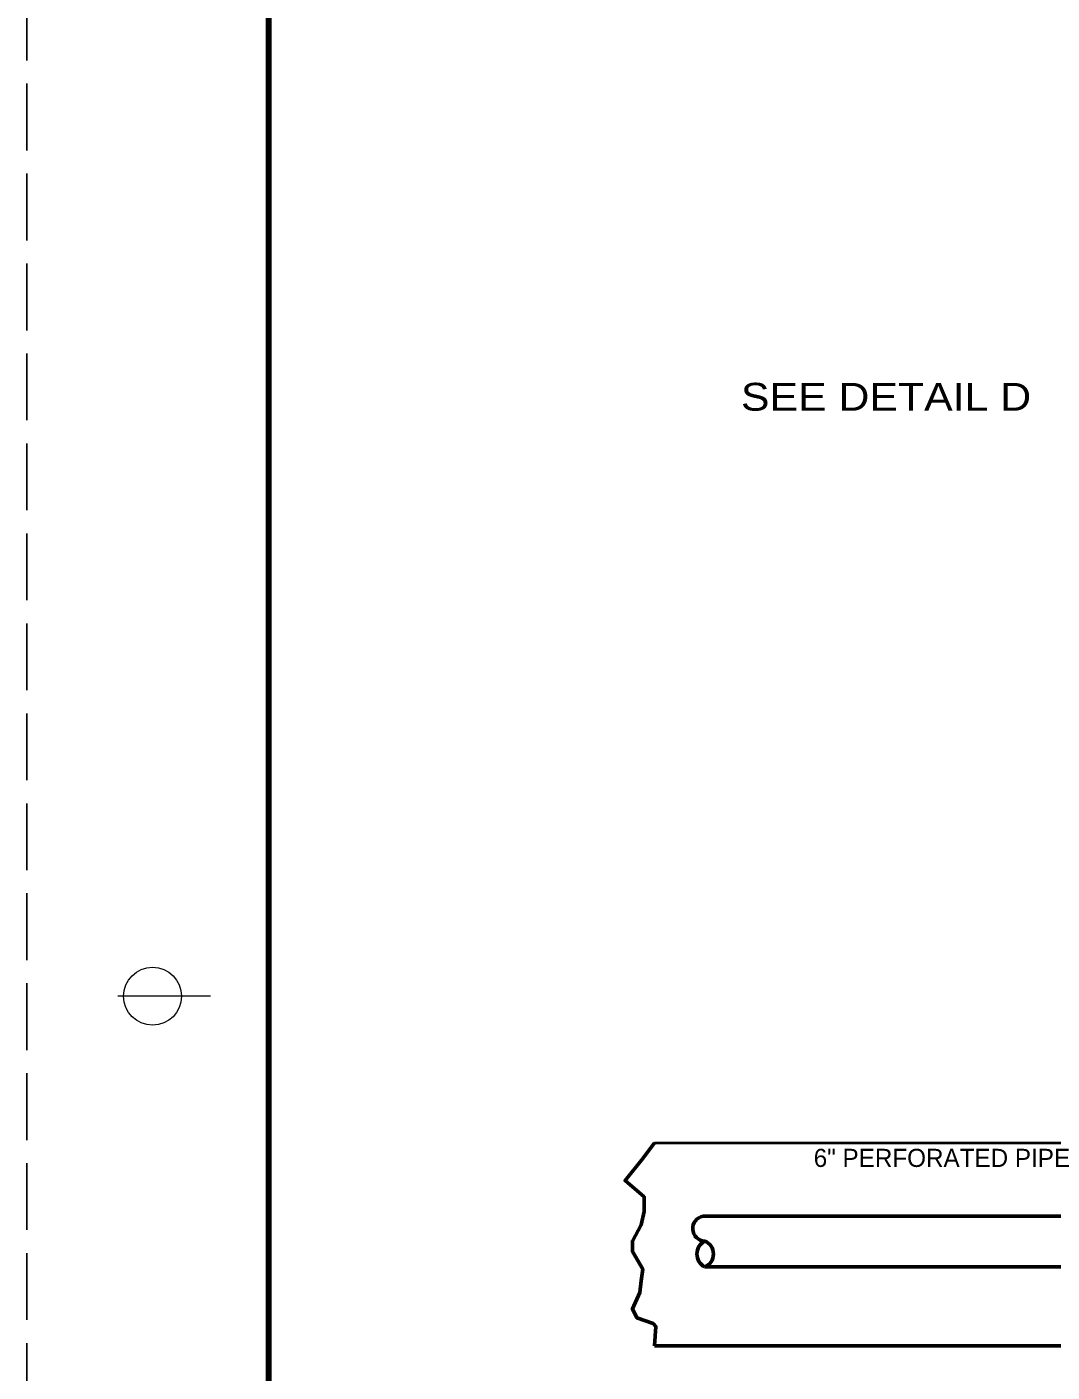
# Model space of a CAD drawing. Extents: x -48732 to -48696.6, y -117659.8 to -117637.8.
# Drawn here: x -48730.39 to -48725.97, y -117654.27 to -117648.47 of the extents above; entities that cross this region are included whole.
import ezdxf

# ---------------------------------------------------------------- set-up
doc = ezdxf.new("R2010")
doc.units = 0
doc.header["$LTSCALE"] = 0.048
doc.linetypes.add('LONG_DASHED', pattern=[7.5, 6, -1.5])
for name, color, linetype, lineweight in [('1', 7, 'Continuous', 25), ('11', 7, 'Continuous', 25), ('24', 7, 'Continuous', 40), ('3', 7, 'Continuous', 35)]:
    doc.layers.add(name, color=color, linetype=linetype, lineweight=lineweight)

msp = doc.modelspace()

# ---------------------------------------------------------------- linework, layer by layer
at = {"layer": '1', "linetype": 'LONG_DASHED'}
msp.add_line((-48730.38992, -117637.84817), (-48730.38992, -117659.84817), dxfattribs=at)
at = {"layer": '1', "lineweight": 158}
msp.add_line((-48729.34825, -117638.34817), (-48729.34825, -117659.34817), dxfattribs=at)
at = {"layer": '1', "lineweight": 13}
msp.add_line((-48729.59825, -117652.64817), (-48729.99825, -117652.64817), dxfattribs=at)
msp.add_circle((-48729.84825, -117652.64817), 0.125, dxfattribs=at)
at = {"layer": '24'}
msp.add_line((-48727.68467, -117653.27983), (-48724.86633, -117653.27983), dxfattribs=at)
at = {"layer": '24', "lineweight": 53}
for p, q in [((-48727.475, -117653.59708), (-48724.86633, -117653.59708)), ((-48727.46867, -117653.81517), (-48722.9295, -117653.81517)), ((-48727.68467, -117654.15533), (-48721.92617, -117654.15533))]:
    msp.add_line(p, q, dxfattribs=at)
msp.add_lwpolyline([(-48727.68467, -117653.27983), (-48727.7355, -117653.34817), (-48727.81167, -117653.4435), (-48727.72908, -117653.51333), (-48727.72908, -117653.57692), (-48727.74183, -117653.63417), (-48727.77983, -117653.704), (-48727.77983, -117653.7485), (-48727.7355, -117653.82483), (-48727.74183, -117653.87567), (-48727.74817, -117653.9265), (-48727.77983, -117653.99633), (-48727.76083, -117654.0345), (-48727.691, -117654.06), (-48727.67833, -117654.07267), (-48727.68467, -117654.15533)], dxfattribs=at)
for centre, radius, start, end in [((-48727.46646, -117653.65023), 0.05384, 99.15625, 267.64039), ((-48727.4391, -117653.75963), 0.06298, 118.01274, 241.98725), ((-48727.49016, -117653.75963), 0.05961, 291.12209, 68.87791)]:
    msp.add_arc(centre, radius, start, end, dxfattribs=at)

# ---------------------------------------------------------------- texts
at = {"layer": '11'}
msp.add_text('6" PERFORATED PIPE', height=0.07812, dxfattribs=at).set_placement((-48726.9985, -117653.38433))
at = {"layer": '3', "width": 1.15}
msp.add_text('SEE DETAIL D', height=0.12, dxfattribs=at).set_placement((-48727.31217, -117650.12267))

doc.saveas('drawing.dxf')
